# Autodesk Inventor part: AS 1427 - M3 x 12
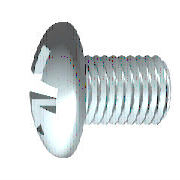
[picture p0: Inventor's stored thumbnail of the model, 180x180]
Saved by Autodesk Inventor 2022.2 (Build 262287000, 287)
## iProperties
Created: 2021-02
Part Number: AS 1427 - M3 x 12
Material: Acciaio, Dolce
Description: Pozidriv Viti metriche ISO
Document SubType Name: Modeling
Standard: AS 1427
Designer: 18907419
Standards Organization: AS
Language: it-IT
Size Designation: M3 x 12
Categories: <MemberInstance><Categories><Category DisplayName="Elementi di fissaggio" InternalName="e4da775c-781d-43d5-af7c-5136215cf5a6" Mnemonic="FSTN"><Category DisplayN
Density: 7.85 g/cm^3
Appearance: Semilucidato
IsCustomPart: 0
Author: 18907419
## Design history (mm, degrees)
body "Solid1"
workplane "Work Plane3"
sketch "Schizzo2"
  geometry: L1 (-4.2, 0)-(4.2, 0) reference; L2 (0, -4.2)-(0, 4.2) reference; L3 (0, 1.575)-(0, 0); L4 (0, 0)-(1.575, 0); L5 (0, 0)-(2.121, 2.121); L6 (0.35, 1.536)-(0.281, 0.474); L7 (1.536, 0.35)-(0.474, 0.281); L8 (0.35, -1.536)-(0.281, -0.474); L9 (1.536, -0.35)-(0.474, -0.281); L10 (-0.35, 1.536)-(-0.281, 0.474); L11 (-1.536, 0.35)-(-0.474, 0.281); L12 (-1.536, -0.35)-(-0.474, -0.281); L13 (-0.35, -1.536)-(-0.281, -0.474); A1 r 0.473 centre (0, 0) between (0.473, 0) and (0, 0.473); A2 r 1.575 centre (0, 0) between (1.575, 0) and (1.536, 0.35); A3 r 1.575 centre (0, 0) between (0.35, 1.536) and (0, 1.575); A4 r 1.575 centre (0, 0) between (1.536, 0.35) and (0.35, 1.536); A5 r 1.575 centre (0, 0) between (0, -1.575) and (0.35, -1.536); A6 r 1.575 centre (0, 0) between (0.35, -1.536) and (1.536, -0.35); A7 r 1.575 centre (0, 0) between (1.536, -0.35) and (1.575, 0); A8 r 1.575 centre (0, 0) between (-1.536, 0.35) and (-1.575, 0); A9 r 1.575 centre (0, 0) between (-0.35, 1.536) and (-1.536, 0.35); A10 r 1.575 centre (0, 0) between (0, 1.575) and (-0.35, 1.536); A11 r 1.575 centre (0, 0) between (-1.575, 0) and (-1.536, -0.35); A12 r 1.575 centre (0, 0) between (-1.536, -0.35) and (-0.35, -1.536); A13 r 1.575 centre (0, 0) between (-0.35, -1.536) and (0, -1.575); A14 r 0.551 centre (0, 0) between (0.551, 0) and (0, 0.551); A15 r 0.181 centre (0.462, 0.462) between (0.281, 0.474) and (0.474, 0.281); A16 r 0.181 centre (0.462, -0.462) between (0.474, -0.281) and (0.281, -0.474); A17 r 0.181 centre (-0.462, 0.462) between (-0.474, 0.281) and (-0.281, 0.474); A18 r 0.181 centre (-0.462, -0.462) between (-0.281, -0.474) and (-0.474, -0.281); 1 further point
  constraints: 38 point on circle, 22 end point, 19 symmetric about line, 18 centre point, 4 coincident, 3 collinear, 3 point on line, 3 tangent, 1 perpendicular, 21 other
  dimensions: "d4" = 45 deg angle of L5 L4; "d5" = 0.945 diameter of A1 (= 0.3 x SDM); "d6" = 3.15 diameter of A4 (= SDM); "d7" = 0.35 distance from line of L6.start L3 (= 0.5 x SBR); "d14" = 1.1025 diameter of A14 (= 0.35 x SDM)
extrude "Intaglio" join sketch "Schizzo2" taper "d15" = 5 deg; stored distance "d54" = 10
revolve "Taglio" stored, may be unused: angle "d56" = 90 deg
revolve "Corpo" stored, may be unused: angle "d18" = 90 deg
workplane "Work Plane1"
sketch "Schizzo1"
  geometry: L1 (12, 0)-(12, 1.5); L2 (12, 1.5)-(1, 1.5); L3 (3.962, 5.08)-(3.962, 5.08); L4 (-2.16, 0)-(-2.16, 3); L5 (-1.948, 1.47)-(-0.809, 0.902); L6 (-0.809, 0.902)-(-0.33, 0); L7 (-0.33, 0)-(12, 0); L8 (-5.27, 0)-(14.878, 0) reference; L9 (0, -1.016)-(0, 6.096) reference; L10 (-1.948, 1.47)-(-2.16, 1.575); L11 (-1.21, 3)-(-2.16, 3); L12 (-1.21, 3)-(0, 3); L13 (0, 3)-(0, 1.347); L14 (0, 1.347)-(0.693, 1.347); L15 (0.693, 1.347)-(1, 1.5); L16 (1, 1.5)-(0, 1.5); A1 r 5.21 centre (3.05, 0) between (-1.21, 3) and (-2.16, 0)
  constraints: 28 end point, 5 point on line, 4 collinear, 4 point on circle, 3 parallel, 2 perpendicular, 1 centre point, 1 horizontal, 1 tangent
  dimensions: "d1" = 3 diameter of L2 L7 (= GD); "d2" = 1.83 distance from line of L6.end L4 (= STI); "d11" = 3.15 diameter of L10.end L7 (= SDM); "d12" = 62 deg angle of L6 L7; "d13" = 26.5 deg angle of L5 L7; "d17" = 6 diameter of L12.end L7 (= KOD); "d19" = 0.01 deg angle of L12 L7 (= KEWI); "d20" = 2.16 distance between parallel lines of L4 L13 (= KOH); "d21" = 5.21 radius of A1 (= KR); "d23" = 2.6935 diameter of L14 L7 (= BDM); "d24" = 11 distance of L1.end L2.end (= GEL); "d25" = 0.30673 horizontal distance of L14.end L2.end (= GAL); "d28" = 12 distance between parallel lines of L1 L13 (= NLG)
fillet "Raccordo1" dims "d29" = 1.2 (= RR)
fillet "Raccordo2" dims "d16" = 0.14 (= 0.2 x SBR)
feature "Filettatura" dims "d8" = 11 (= GEL), "d9" = 0
chamfer "Smusso1" distance "d26" = 0.30673 (= -0.5 x SPD + 0.5 x GD); stored, may be unused: second distance "d27" = 0.30683 (computed from GUL), angle "d78" = 45 deg
other parameters: "GD" = 3 (= NND) [user parameter; used in 2 equation terms], "NLG" = 12 [user parameter; used in 1 equation term], "GEL" = 11 [user parameter; used in 2 equation terms], "KOD" = 6 [user parameter; used in 1 equation term], "KOH" = 2.16 [user parameter; used in 2 equation terms], "SDM" = 3.15 [user parameter; used in 4 equation terms], "STI" = 1.83 [user parameter; used in 1 equation term], "SBR" = 0.7 [user parameter; used in 2 equation terms], "GAL" = 0.30673 (= 0.61345 x PTC) [user parameter; used in 1 equation term], "SPD" = 2.38655 (= NND - 1.2269 x PTC) [user parameter; used in 1 equation term], "KEWI" = 0.01 deg [user parameter; used in 1 equation term], "d3" = -2.16 (= -KOH), "d10" = 0, "KR" = 5.21 [user parameter; used in 1 equation term], "BDM" = 2.6935 [user parameter; used in 1 equation term], "GUL" = 0.30673 (= 0.61345 x PTC) [user parameter; used in 1 equation term], "RR" = 1.2 [user parameter; used in 1 equation term], "d79" = 0, "d80" = 0, "PTC" = 0.5 [user parameter; used in 5 equation terms], "THREADDIA" = 3 [user parameter; used in 1 equation term], "TOA" = 30 deg [user parameter], "NND" = 3 [user parameter; used in 2 equation terms], "GD1" = 2.38655 (= THREADDIA - 1.2269 x PTC) [user parameter]
